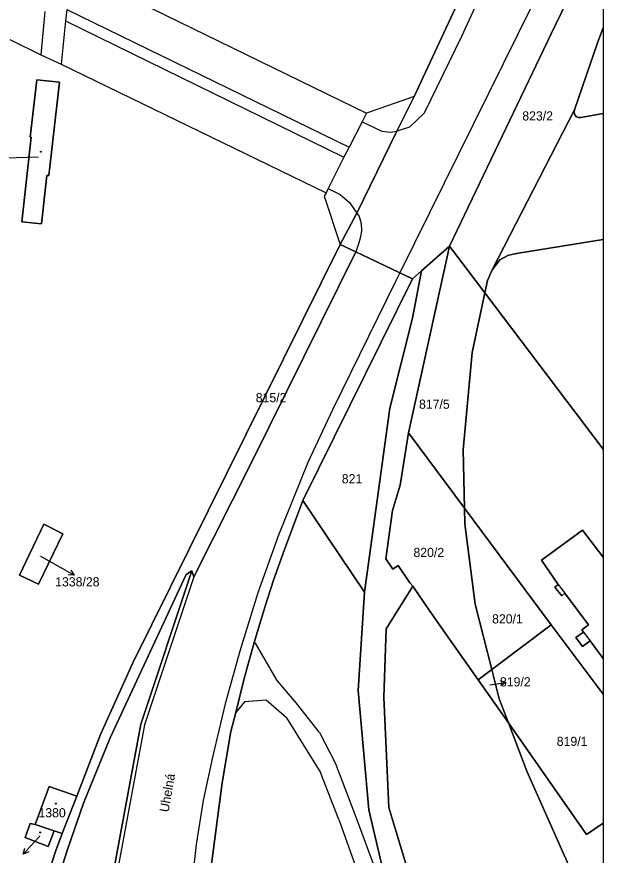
# Model space of a CAD drawing. Extents: x -598934 to -598196, y -1162208 to -1161502.
# Drawn here: x -598304.2 to -598195.6, y -1161913.2 to -1161757.9 of the extents above; entities that cross this region are included whole.
import ezdxf

# ---------------------------------------------------------------- set-up
doc = ezdxf.new("R2010")
doc.units = 0
for name, color, linetype in [('KN_CAR_KR', 7, 'Continuous'), ('KN_KULTURY', 7, 'Continuous'), ('KN_PARC_CIS_POM', 7, 'Continuous'), ('KN_PARC_CIS_POZ', 7, 'Continuous'), ('KN_PARC_CIS_STAV', 7, 'Continuous'), ('KN_PARC_PLOCHA', 7, 'Continuous'), ('KN_ULICE', 7, 'Continuous'), ('PARC_C_SIPKA', 7, 'Continuous'), ('parcely_l', 7, 'Continuous')]:
    doc.layers.add(name, color=color, linetype=linetype)

msp = doc.modelspace()

# ---------------------------------------------------------------- linework, layer by layer
at = {"layer": 'KN_CAR_KR'}
for points in [[(-598294.04, -1161749.08), (-598239.45, -1161775.78)], [(-598205.9, -1161750), (-598233.27, -1161805.34)], [(-598216.5, -1161750), (-598221.81, -1161761.59)], [(-598299.04, -1161756.95), (-598299.79, -1161764.96)], [(-598294.99, -1161756.56), (-598295.19, -1161758.67)], [(-598294.99, -1161756.56), (-598242.66, -1161782.11)], [(-598295.19, -1161758.67), (-598296.04, -1161766.73)], [(-598295.19, -1161758.67), (-598243.61, -1161783.96)], [(-598305.52, -1161762.14), (-598299.79, -1161764.96)], [(-598221.81, -1161761.59), (-598228.77, -1161775.81)], [(-598299.79, -1161764.96), (-598296.04, -1161766.73)], [(-598296.04, -1161766.73), (-598246.92, -1161790.53)], [(-598230.6, -1161772.67), (-598239.45, -1161775.78)], [(-598239.45, -1161775.78), (-598240.24, -1161777.4)], [(-598228.77, -1161775.81), (-598231.44, -1161778.37)], [(-598240.24, -1161777.4), (-598242.66, -1161782.11)], [(-598240.24, -1161777.4), (-598236.61, -1161779.09)], [(-598236.61, -1161779.09), (-598235.02, -1161779.31)], [(-598235.02, -1161779.31), (-598233.81, -1161779.13)], [(-598231.44, -1161778.37), (-598233.81, -1161779.13)], [(-598242.66, -1161782.11), (-598243.61, -1161783.96)], [(-598243.61, -1161783.96), (-598246.51, -1161789.74)], [(-598246.51, -1161789.74), (-598246.92, -1161790.53)], [(-598246.51, -1161789.74), (-598244.3, -1161790.83)], [(-598246.92, -1161790.53), (-598247.27, -1161791.15)], [(-598247.27, -1161791.15), (-598244.3, -1161800.11)], [(-598244.3, -1161790.83), (-598242.58, -1161792.35)], [(-598242.58, -1161792.35), (-598241.25, -1161794.31)], [(-598241.25, -1161794.31), (-598240.76, -1161794.93)], [(-598240.76, -1161794.93), (-598240.41, -1161796.24)], [(-598240.41, -1161796.24), (-598240.36, -1161797.54)], [(-598240.36, -1161797.54), (-598240.55, -1161798.69)], [(-598240.55, -1161798.69), (-598240.85, -1161799.82)], [(-598240.85, -1161799.82), (-598241.41, -1161801.48)], [(-598233.27, -1161805.34), (-598234.07, -1161806.95)], [(-598234.07, -1161806.95), (-598245.76, -1161830.72)], [(-598245.76, -1161830.72), (-598250.28, -1161840.47)], [(-598250.28, -1161840.47), (-598253.01, -1161847.22)], [(-598253.01, -1161847.22), (-598255.74, -1161853.97)], [(-598255.74, -1161853.97), (-598259.57, -1161864.61)], [(-598271.45, -1161861.7), (-598275.13, -1161872.8)], [(-598203.9, -1161863.08), (-598202.65, -1161864.73)], [(-598259.57, -1161864.61), (-598262.9, -1161875.43)], [(-598199.22, -1161871.92), (-598198, -1161873.51)], [(-598275.13, -1161872.8), (-598280.58, -1161889.1)], [(-598260, -1161873.94), (-598260.25, -1161873.84)], [(-598256.01, -1161880.85), (-598260, -1161873.94)], [(-598262.9, -1161875.43), (-598265.59, -1161885.22)], [(-598252.49, -1161884.99), (-598256.01, -1161880.85)], [(-598262.05, -1161884.83), (-598263.67, -1161886.82)], [(-598258.03, -1161884.55), (-598262.05, -1161884.83)], [(-598254.27, -1161887.77), (-598258.03, -1161884.55)], [(-598265.59, -1161885.22), (-598267.97, -1161895.09)], [(-598248.16, -1161890.54), (-598252.49, -1161884.99)], [(-598254.27, -1161887.77), (-598247.98, -1161897.95)], [(-598280.58, -1161889.1), (-598285.73, -1161917.07)], [(-598248.16, -1161890.54), (-598245.25, -1161896.15)], [(-598267.97, -1161895.09), (-598269.67, -1161903.13)], [(-598245.25, -1161896.15), (-598241.34, -1161906.34)], [(-598244.54, -1161906.64), (-598247.98, -1161897.95)], [(-598269.67, -1161903.13), (-598271.02, -1161911.25)], [(-598244.54, -1161906.64), (-598236.57, -1161928.91)], [(-598241.34, -1161906.34), (-598236.54, -1161919.37)], [(-598271.02, -1161911.25), (-598272.01, -1161920.23)]]:
    msp.add_lwpolyline(points, dxfattribs=at)
at = {"layer": 'KN_KULTURY'}
for centre, radius in [((-598299.78, -1161782.93), 0.09), ((-598299.78, -1161782.93), 0.0398), ((-598297, -1161903.68), 0.09), ((-598297, -1161903.68), 0.0398), ((-598299.9, -1161909.03), 0.09), ((-598299.9, -1161909.03), 0.0398)]:
    msp.add_circle(centre, radius, dxfattribs=at)
at = {"layer": 'KN_PARC_PLOCHA'}
for points in [[(-598195.56, -1161741.36), (-598196.92, -1161744.05), (-598198.54, -1161747.25), (-598205.22, -1161761.08), (-598224.02, -1161800.44), (-598229.26, -1161804.97), (-598230.88, -1161806.47), (-598233.27, -1161805.34), (-598241.41, -1161801.48), (-598244.3, -1161800.11), (-598241.25, -1161794.31), (-598233.81, -1161779.13), (-598230.6, -1161772.67), (-598220.86, -1161751.71), (-598195.56, -1161700.65)], [(-598195.56, -1161751.33), (-598195.56, -1161759.97), (-598196.64, -1161762.77), (-598200.89, -1161775.19), (-598216.12, -1161804.81), (-598216.98, -1161806.75), (-598217.48, -1161809.08), (-598224.02, -1161800.44), (-598205.22, -1161761.08), (-598198.54, -1161747.25)], [(-598195.56, -1161775.85), (-598199.71, -1161776.59), (-598200.14, -1161776.59), (-598200.54, -1161776.44), (-598200.84, -1161776.12), (-598200.96, -1161775.67), (-598200.89, -1161775.19), (-598196.64, -1161762.77), (-598195.56, -1161759.97)], [(-598296.32, -1161770.06), (-598300.55, -1161769.58), (-598301.76, -1161780.21), (-598301.56, -1161780.24), (-598303.32, -1161795.9), (-598299.67, -1161796.29), (-598298.67, -1161787.31), (-598298.27, -1161787.35)], [(-598296.32, -1161770.06), (-598298.27, -1161787.35), (-598298.67, -1161787.31), (-598299.67, -1161796.29), (-598303.32, -1161795.9), (-598301.56, -1161780.24), (-598301.76, -1161780.21), (-598300.55, -1161769.58)], [(-598195.56, -1161775.85), (-598195.56, -1161799.19), (-598211.26, -1161801.71), (-598213.13, -1161802.11), (-598214.74, -1161802.98), (-598216.12, -1161804.81), (-598200.89, -1161775.19), (-598200.96, -1161775.67), (-598200.84, -1161776.12), (-598200.54, -1161776.44), (-598200.14, -1161776.59), (-598199.71, -1161776.59)], [(-598195.56, -1161838.01), (-598217.48, -1161809.08), (-598216.98, -1161806.75), (-598216.12, -1161804.81), (-598214.74, -1161802.98), (-598213.13, -1161802.11), (-598211.26, -1161801.71), (-598195.56, -1161799.19)], [(-598217.48, -1161809.08), (-598219.82, -1161820.1), (-598221.51, -1161838.16), (-598221.27, -1161848.98), (-598231.66, -1161834.99), (-598224.02, -1161800.44)], [(-598239.81, -1161864.53), (-598251.23, -1161847.53), (-598230.88, -1161806.47), (-598229.26, -1161804.97), (-598230.88, -1161813.77), (-598235.09, -1161830.41)], [(-598195.56, -1161838.01), (-598195.56, -1161858.02), (-598199.43, -1161853.03), (-598207.03, -1161858.6), (-598203.9, -1161863.08), (-598204.5, -1161863.61), (-598203.21, -1161865.21), (-598202.65, -1161864.73), (-598198.3, -1161870.55), (-598199.52, -1161871.52), (-598199.22, -1161871.92), (-598200.64, -1161872.9), (-598199.39, -1161874.55), (-598198, -1161873.51), (-598195.56, -1161876.78), (-598195.56, -1161883.42), (-598205.2, -1161870.59), (-598221.27, -1161848.98), (-598221.51, -1161838.16), (-598219.82, -1161820.1), (-598217.48, -1161809.08)], [(-598221.27, -1161848.98), (-598221.2, -1161851.87), (-598219.29, -1161866.76), (-598216.23, -1161878.86), (-598218.74, -1161880.74), (-598224.02, -1161873.25), (-598227.79, -1161867.85), (-598230.86, -1161863.41), (-598231.38, -1161862.78), (-598233.58, -1161859.55), (-598234.57, -1161860.23), (-598235.87, -1161858.33), (-598234.62, -1161849.4), (-598233.2, -1161844.72), (-598231.66, -1161834.99)], [(-598205.2, -1161870.59), (-598216.23, -1161878.86), (-598219.29, -1161866.76), (-598221.2, -1161851.87), (-598221.27, -1161848.98)], [(-598295.71, -1161853.69), (-598300.22, -1161863.05), (-598303.76, -1161861.39), (-598299.23, -1161851.93)], [(-598295.71, -1161853.69), (-598299.23, -1161851.93), (-598303.76, -1161861.39), (-598300.22, -1161863.05)], [(-598195.56, -1161858.02), (-598195.56, -1161876.78), (-598198, -1161873.51), (-598199.39, -1161874.55), (-598200.64, -1161872.9), (-598199.22, -1161871.92), (-598199.52, -1161871.52), (-598198.3, -1161870.55), (-598202.65, -1161864.73), (-598203.21, -1161865.21), (-598204.5, -1161863.61), (-598203.9, -1161863.08), (-598207.03, -1161858.6), (-598199.43, -1161853.03)], [(-598288.1, -1161990.75), (-598322.07, -1161998.71), (-598315.42, -1161976.86), (-598294.91, -1161912.37), (-598291.89, -1161903.62), (-598286.96, -1161891.51), (-598272.85, -1161861.26), (-598271.79, -1161860.57), (-598281.27, -1161888.97), (-598286.42, -1161916.94), (-598287.31, -1161938.24), (-598286.7, -1161955.76), (-598285.36, -1161975.57), (-598285.26, -1161978.39), (-598285.61, -1161982.99)], [(-598218.74, -1161880.74), (-598213.14, -1161888.75), (-598209.7, -1161897.69), (-598195.56, -1161929.46), (-598195.56, -1161958.89), (-598212.25, -1161958.32), (-598217.75, -1161955.48), (-598221.97, -1161948.62), (-598235.3, -1161904.43), (-598236.24, -1161883.94), (-598235.79, -1161871.31), (-598230.86, -1161863.41), (-598227.79, -1161867.85), (-598224.02, -1161873.25)], [(-598195.56, -1161883.42), (-598195.56, -1161907.3), (-598198.69, -1161909.42), (-598213.14, -1161888.75), (-598214.86, -1161884.28), (-598216.23, -1161878.86), (-598205.2, -1161870.59)], [(-598213.14, -1161888.75), (-598218.74, -1161880.74), (-598216.23, -1161878.86), (-598214.86, -1161884.28)], [(-598213.14, -1161888.75), (-598198.69, -1161909.42), (-598195.56, -1161907.3), (-598195.56, -1161929.46), (-598209.7, -1161897.69)], [(-598293.13, -1161902.29), (-598295.82, -1161909.22), (-598297.28, -1161908.74), (-598300.83, -1161907.58), (-598300.64, -1161907.08), (-598298.26, -1161900.52)], [(-598300.83, -1161907.58), (-598297.28, -1161908.74), (-598298.4, -1161911.61), (-598302.67, -1161909.95), (-598301.75, -1161907.34)]]:
    msp.add_lwpolyline(points, close=True, dxfattribs=at)
for points in [[(-598220.86, -1161751.71), (-598230.6, -1161772.67), (-598233.81, -1161779.13), (-598241.25, -1161794.31), (-598244.3, -1161800.11), (-598282.73, -1161877.6), (-598288.74, -1161890.9), (-598293.13, -1161902.29), (-598298.26, -1161900.52), (-598300.64, -1161907.08), (-598300.83, -1161907.58), (-598301.75, -1161907.34), (-598302.67, -1161909.95), (-598298.4, -1161911.61), (-598297.28, -1161908.74), (-598295.82, -1161909.22), (-598296.97, -1161912.35), (-598308.6, -1161948.05)], [(-598308.6, -1161948.05), (-598296.97, -1161912.35), (-598295.82, -1161909.22), (-598293.13, -1161902.29), (-598288.74, -1161890.9), (-598282.73, -1161877.6), (-598244.3, -1161800.11), (-598241.41, -1161801.48), (-598260.68, -1161840.37), (-598271.45, -1161861.7), (-598271.79, -1161860.57), (-598272.85, -1161861.26), (-598286.96, -1161891.51), (-598291.89, -1161903.62), (-598294.91, -1161912.37), (-598315.42, -1161976.86)], [(-598235.06, -1161921.69), (-598238.98, -1161904.83), (-598240.99, -1161882.72), (-598239.81, -1161864.53), (-598235.09, -1161830.41), (-598230.88, -1161813.77), (-598229.26, -1161804.97), (-598224.02, -1161800.44), (-598231.66, -1161834.99), (-598233.2, -1161844.72), (-598234.62, -1161849.4), (-598235.87, -1161858.33), (-598234.57, -1161860.23), (-598233.58, -1161859.55), (-598231.38, -1161862.78), (-598230.86, -1161863.41), (-598235.79, -1161871.31), (-598236.24, -1161883.94), (-598235.3, -1161904.43), (-598221.97, -1161948.62)], [(-598286.42, -1161916.94), (-598281.27, -1161888.97), (-598271.79, -1161860.57), (-598271.45, -1161861.7), (-598260.68, -1161840.37), (-598241.41, -1161801.48), (-598233.27, -1161805.34), (-598230.88, -1161806.47), (-598251.23, -1161847.53), (-598254.62, -1161856.63), (-598256.66, -1161862.28), (-598258.22, -1161867.08), (-598260.25, -1161873.84), (-598262.11, -1161880.5), (-598263.67, -1161886.82), (-598264.54, -1161890.34), (-598266.17, -1161899.82), (-598268.4, -1161916.78)], [(-598268.4, -1161916.78), (-598266.17, -1161899.82), (-598264.54, -1161890.34), (-598263.67, -1161886.82), (-598262.11, -1161880.5), (-598260.25, -1161873.84), (-598258.22, -1161867.08), (-598256.66, -1161862.28), (-598254.62, -1161856.63), (-598251.23, -1161847.53), (-598239.81, -1161864.53), (-598240.99, -1161882.72), (-598238.98, -1161904.83), (-598235.06, -1161921.69)]]:
    msp.add_lwpolyline(points, dxfattribs=at)
at = {"layer": 'PARC_C_SIPKA'}
for points in [[(-598300.25, -1161783.95), (-598308.51, -1161784.18), (-598311.51, -1161784.26)], [(-598299.84, -1161857.85), (-598296.22, -1161859.9), (-598293.61, -1161861.38)], [(-598294.23, -1161860.45), (-598293.61, -1161861.38), (-598294.73, -1161861.32)], [(-598216.57, -1161881.67), (-598213.6, -1161881.24)], [(-598214.66, -1161880.89), (-598213.6, -1161881.24), (-598214.52, -1161881.88)], [(-598299.94, -1161909.69), (-598301.01, -1161910.83), (-598303.07, -1161913.02)], [(-598302.02, -1161912.63), (-598303.07, -1161913.02), (-598302.74, -1161911.94)]]:
    msp.add_lwpolyline(points, dxfattribs=at)
at = {"layer": 'parcely_l'}
for points in [[(-598195.56, -1161700.65), (-598220.86, -1161751.71), (-598230.6, -1161772.67), (-598233.81, -1161779.13), (-598241.25, -1161794.31), (-598244.3, -1161800.11)], [(-598224.02, -1161800.44), (-598205.22, -1161761.08), (-598198.54, -1161747.25)], [(-598195.56, -1161751.33), (-598195.56, -1161759.97)], [(-598195.56, -1161759.97), (-598196.64, -1161762.77), (-598200.89, -1161775.19)], [(-598195.56, -1161759.97), (-598195.56, -1161775.85)], [(-598296.32, -1161770.06), (-598298.27, -1161787.35), (-598298.67, -1161787.31), (-598299.67, -1161796.29), (-598303.32, -1161795.9), (-598301.56, -1161780.24), (-598301.76, -1161780.21), (-598300.55, -1161769.58), (-598296.32, -1161770.06)], [(-598216.12, -1161804.81), (-598200.89, -1161775.19)], [(-598200.89, -1161775.19), (-598200.96, -1161775.67), (-598200.84, -1161776.12), (-598200.54, -1161776.44), (-598200.14, -1161776.59), (-598199.71, -1161776.59), (-598195.56, -1161775.85)], [(-598195.56, -1161775.85), (-598195.56, -1161799.19)], [(-598195.56, -1161799.19), (-598211.26, -1161801.71), (-598213.13, -1161802.11), (-598214.74, -1161802.98), (-598216.12, -1161804.81)], [(-598195.56, -1161799.19), (-598195.56, -1161838.01)], [(-598244.3, -1161800.11), (-598282.73, -1161877.6), (-598288.74, -1161890.9), (-598293.13, -1161902.29)], [(-598241.41, -1161801.48), (-598244.3, -1161800.11)], [(-598224.02, -1161800.44), (-598231.66, -1161834.99)], [(-598229.26, -1161804.97), (-598224.02, -1161800.44)], [(-598224.02, -1161800.44), (-598217.48, -1161809.08)], [(-598241.41, -1161801.48), (-598260.68, -1161840.37), (-598271.45, -1161861.7), (-598271.79, -1161860.57)], [(-598230.88, -1161806.47), (-598233.27, -1161805.34), (-598241.41, -1161801.48)], [(-598239.81, -1161864.53), (-598235.09, -1161830.41), (-598230.88, -1161813.77), (-598229.26, -1161804.97)], [(-598229.26, -1161804.97), (-598230.88, -1161806.47)], [(-598216.12, -1161804.81), (-598216.98, -1161806.75), (-598217.48, -1161809.08)], [(-598251.23, -1161847.53), (-598230.88, -1161806.47)], [(-598221.27, -1161848.98), (-598221.51, -1161838.16), (-598219.82, -1161820.1), (-598217.48, -1161809.08)], [(-598217.48, -1161809.08), (-598195.56, -1161838.01)], [(-598231.66, -1161834.99), (-598233.2, -1161844.72), (-598234.62, -1161849.4), (-598235.87, -1161858.33), (-598234.57, -1161860.23), (-598233.58, -1161859.55), (-598231.38, -1161862.78), (-598230.86, -1161863.41)], [(-598221.27, -1161848.98), (-598231.66, -1161834.99)], [(-598195.56, -1161838.01), (-598195.56, -1161858.02)], [(-598268.4, -1161916.78), (-598266.17, -1161899.82), (-598264.54, -1161890.34), (-598263.67, -1161886.82), (-598262.11, -1161880.5), (-598260.25, -1161873.84), (-598258.22, -1161867.08), (-598256.66, -1161862.28), (-598254.62, -1161856.63), (-598251.23, -1161847.53)], [(-598251.23, -1161847.53), (-598239.81, -1161864.53)], [(-598205.2, -1161870.59), (-598221.27, -1161848.98)], [(-598216.23, -1161878.86), (-598219.29, -1161866.76), (-598221.2, -1161851.87), (-598221.27, -1161848.98)], [(-598295.71, -1161853.69), (-598299.23, -1161851.93), (-598303.76, -1161861.39), (-598300.22, -1161863.05), (-598295.71, -1161853.69)], [(-598195.56, -1161876.78), (-598198, -1161873.51), (-598199.39, -1161874.55), (-598200.64, -1161872.9), (-598199.22, -1161871.92), (-598199.52, -1161871.52), (-598198.3, -1161870.55), (-598202.65, -1161864.73), (-598203.21, -1161865.21), (-598204.5, -1161863.61), (-598203.9, -1161863.08), (-598207.03, -1161858.6), (-598199.43, -1161853.03), (-598195.56, -1161858.02)], [(-598195.56, -1161858.02), (-598195.56, -1161876.78)], [(-598288.1, -1161990.75), (-598322.07, -1161998.71), (-598315.42, -1161976.86), (-598294.91, -1161912.37), (-598291.89, -1161903.62), (-598286.96, -1161891.51), (-598272.85, -1161861.26), (-598271.79, -1161860.57)], [(-598271.79, -1161860.57), (-598281.27, -1161888.97), (-598286.42, -1161916.94), (-598287.31, -1161938.24), (-598286.7, -1161955.76), (-598285.36, -1161975.57), (-598285.26, -1161978.39), (-598285.61, -1161982.99), (-598288.1, -1161990.75)], [(-598195.56, -1161964.54), (-598216.17, -1161963.98), (-598224.5, -1161956.39), (-598235.06, -1161921.69), (-598238.98, -1161904.83), (-598240.99, -1161882.72), (-598239.81, -1161864.53)], [(-598230.86, -1161863.41), (-598235.79, -1161871.31), (-598236.24, -1161883.94), (-598235.3, -1161904.43), (-598221.97, -1161948.62), (-598217.75, -1161955.48), (-598212.25, -1161958.32), (-598195.56, -1161958.89)], [(-598218.74, -1161880.74), (-598224.02, -1161873.25), (-598227.79, -1161867.85), (-598230.86, -1161863.41)], [(-598216.23, -1161878.86), (-598205.2, -1161870.59)], [(-598195.56, -1161883.42), (-598205.2, -1161870.59)], [(-598195.56, -1161876.78), (-598195.56, -1161883.42)], [(-598218.74, -1161880.74), (-598216.23, -1161878.86)], [(-598213.14, -1161888.75), (-598214.86, -1161884.28), (-598216.23, -1161878.86)], [(-598213.14, -1161888.75), (-598218.74, -1161880.74)], [(-598195.56, -1161883.42), (-598195.56, -1161907.3)], [(-598213.14, -1161888.75), (-598198.69, -1161909.42), (-598195.56, -1161907.3)], [(-598195.56, -1161929.46), (-598209.7, -1161897.69), (-598213.14, -1161888.75)], [(-598293.13, -1161902.29), (-598298.26, -1161900.52), (-598300.64, -1161907.08), (-598300.83, -1161907.58)], [(-598293.13, -1161902.29), (-598295.82, -1161909.22)], [(-598300.83, -1161907.58), (-598301.75, -1161907.34), (-598302.67, -1161909.95), (-598298.4, -1161911.61), (-598297.28, -1161908.74)], [(-598297.28, -1161908.74), (-598300.83, -1161907.58)], [(-598195.56, -1161907.3), (-598195.56, -1161929.46)], [(-598295.82, -1161909.22), (-598296.97, -1161912.35), (-598308.6, -1161948.05), (-598321.28, -1161991.38), (-598322.64, -1161996.12), (-598323.03, -1161997.13), (-598323.76, -1161998.16), (-598324.63, -1161998.8), (-598325.46, -1161999.37), (-598326.6, -1161999.69), (-598327.84, -1161999.87), (-598329.17, -1161999.67), (-598330.42, -1161999.13), (-598330.34, -1161999.7), (-598330.87, -1162001.34)], [(-598297.28, -1161908.74), (-598295.82, -1161909.22)]]:
    msp.add_lwpolyline(points, dxfattribs=at)

# ---------------------------------------------------------------- texts
at = {"layer": 'KN_PARC_CIS_POM'}
for s, p in [('1338/27', (-598300.58, -1161783.95)), ('1338/28', (-598300.17, -1161857.85)), ('819/2', (-598216.68, -1161881.67)), ('1338/34', (-598300.27, -1161909.69))]:
    msp.add_text(s, height=0.1, dxfattribs=at).set_placement(p)
at = {"layer": 'KN_PARC_CIS_POZ'}
for s, p in [('823/2', (-598210.56, -1161777.14)), ('815/2', (-598259.96, -1161829.33)), ('817/5', (-598229.7, -1161830.54)), ('821', (-598244.01, -1161844.36)), ('820/2', (-598230.73, -1161858.01)), ('1338/28', (-598297.12, -1161863.45)), ('819/2', (-598214.7, -1161881.98)), ('819/1', (-598204.17, -1161893))]:
    msp.add_text(s, height=1.7, dxfattribs=at).set_placement(p)
at = {"layer": 'KN_PARC_CIS_STAV'}
for s, p in [('820/1', (-598216.16, -1161870.31)), ('1380', (-598300.22, -1161906.23))]:
    msp.add_text(s, height=1.7, dxfattribs=at).set_placement(p)
at = {"layer": 'KN_ULICE'}
msp.add_text('Uhelná', height=1.7, rotation=80.1005, dxfattribs=at).set_placement((-598276.12, -1161905.37))

doc.saveas('drawing.dxf')
